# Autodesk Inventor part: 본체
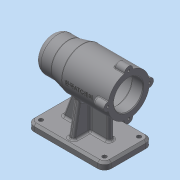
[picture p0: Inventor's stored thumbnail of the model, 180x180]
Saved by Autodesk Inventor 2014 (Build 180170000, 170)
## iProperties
Created: 2019-07
Part Number: 본체
Material: Generic
Document SubType Name: Modeling
Designer: mm
Density: 1 g/cm^3
Appearance: Default
Author: mm
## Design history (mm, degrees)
sketch "스케치1"
  geometry: L1 (-56, 35)-(56, 35); L2 (56, 35)-(56, -35); L3 (56, -35)-(-56, -35); L4 (-56, -35)-(-56, 35); L5 (-56, 35)-(56, -35); L6 (56, 35)-(-56, -35); 1 further point
  constraints: 12 end point, 2 midpoint, 2 parallel, 1 horizontal, 1 perpendicular
  dimensions: "d0" = 112 distance between parallel lines of L2 L4; "d1" = 70 distance between parallel lines of L3 L1
extrude "돌출1" new body sketch "스케치1" distance "d2" = 10; taper "d3" = 0 deg
sketch "스케치2"
  geometry: L1 (56, 80)-(-56, 80); L2 (56, 80)-(56, 105); L3 (56, 105)-(31, 105); L4 (31, 105)-(11, 110); L5 (11, 110)-(-56, 110); L6 (-56, 110)-(-56, 80); L7 (-56, 0)-(56, 0) reference; 1 further point
  constraints: 12 end point, 2 parallel, 2 perpendicular, 1 horizontal, 1 vertical alignment
  dimensions: "d4" = 50 diameter of L3 L1; "d5" = 60 diameter of L5 L1; "d6" = 25 distance from line of L3.end L2; "d7" = 45 distance from line of L4.end L2; "d8" = 80 distance from line of L7 L1.start; "d9" = 112 distance between parallel lines of L2 L6
revolve "회전1" sketch "스케치2" stored, may be unused: angle "d10" = 90 deg
sketch "스케치3"
  geometry: L1 (15.657, 80)-(-15.657, 80); L2 (15.657, 80)-(28, 10); L3 (-15.657, 80)-(-28, 10); L4 (28, 10)-(-28, 10); L5 (35, 0)-(-35, 0) reference; L6 (-35, 10)-(35, 10) reference; L7 (35, 0)-(35, 10) reference; 3 further points
  constraints: 8 end point, 2 midpoint, 1 collinear, 1 horizontal, 1 parallel, 1 vertical alignment
  dimensions: "d11" = 80 distance between parallel lines of L5 L1; "d12" = 100 deg angle of L2 L6; "d13" = 100 deg angle of L6 L3; "d14" = 7 distance from line of L2.end L7
extrude "돌출2" join sketch "스케치3" stored distance "d15" = 8; taper "d16" = 0 deg
sketch "스케치4"
  geometry: L1 (36, 10)-(10.522, 80); L2 (10.522, 80)-(-31, 80); L3 (-31, 80)-(-31, 10); L4 (36, 10)-(-31, 10); L5 (-56, 0)-(-56, 10) reference; L6 (56, 0)-(56, 10) reference; L7 (-56, 10)-(56, 10) reference; L8 (56, 0)-(-56, 0) reference; 1 further point
  constraints: 8 end point, 2 perpendicular, 1 collinear, 1 horizontal
  dimensions: "d17" = 25 distance from line of L3.end L5; "d18" = 20 distance from line of L1.start L6; "d19" = 110 deg angle of L1 L7; "d20" = 80 distance between parallel lines of L2 L8
extrude "돌출3" join sketch "스케치4" stored distance "d21" = 8; taper "d22" = 0 deg
sketch "스케치5"
  geometry: L1 (-56, 80)-(51, 80); L2 (51, 80)-(51, 90.5); L3 (51, 90.5)-(48, 90.5); L4 (48, 90.5)-(48, 96); L5 (48, 96)-(44, 96); L6 (44, 96)-(44, 97.5); L7 (44, 97.5)-(26, 97.5); L8 (26, 97.5)-(26, 101); L9 (26, 101)-(14, 101); L10 (14, 101)-(14, 104); L11 (14, 104)-(-40, 104); L12 (-40, 104)-(-40, 101); L13 (-40, 101)-(-56, 101); L14 (-56, 101)-(-56, 80); L15 (-56, 50)-(-56, 110) reference; L16 (56, 0)-(-56, 0) reference; 1 further point
  constraints: 28 end point, 10 parallel, 3 perpendicular, 1 collinear, 1 horizontal
  dimensions: "d23" = 48 diameter of L11 L1; "d24" = 42 diameter of L9 L1; "d25" = 42 diameter of L13 L1; "d26" = 35 diameter of L7 L1; "d27" = 32 diameter of L5 L1; "d28" = 21 diameter of L3 L1; "d29" = 3 distance between parallel lines of L4 L2; "d30" = 4 distance between parallel lines of L6 L4; "d31" = 18 distance between parallel lines of L8 L6; "d32" = 11.99959 distance between parallel lines of L10 L8; "d33" = 80 distance between parallel lines of L16 L1; "d34" = 16 distance between parallel lines of L12 L14; "d35" = 54 distance between parallel lines of L12 L10
revolve "회전2" sketch "스케치5" stored, may be unused: angle "d36" = 90 deg
sketch "스케치6"
  geometry: C1 r 21 at (0, 0) reference; C2 r 30 at (0, 0); C3 r 6 at (-30, 0); 2 further points
  constraints: 2 centre point, 2 horizontal alignment, 1 coincident, 1 other
  dimensions: "d37" = 60 diameter of C2; "d38" = 6 radius of C3
extrude "돌출4" join sketch "스케치6" distance "d39" = 16; taper "d40" = 0 deg
sketch "스케치7"
  geometry: A1 r 6 centre (0, 0) between (0.6, 5.97) and (0.6, -5.97) reference; 2 further points
  constraints: 1 coincident
hole "구멍1" sketch "스케치7" at (0, 0) diameter "d44" = 3.242; stored, may be unused: countersink angle "d48" = 90 deg, drill point angle "d50" = 118 deg; dims "d45" = 8, "d46" = 4, "d47" = 2, "d49" = 11
fillet "모깎기1" dims "d54" = 10
fillet "모깎기2" dims "d55" = 10
hole "구멍2" diameter "d58" = 6; stored, may be unused: countersink angle "d62" = 90 deg, drill point angle "d64" = 118 deg; dims "d56" = 10, "d57" = 10, "d59" = 8, "d60" = 4, "d61" = 2, "d63" = 11
chamfer "모따기1" distance "d71" = 1; stored, may be unused: second distance "d72" = 2, angle "d73" = 45 deg
fillet "모깎기3" dims "d74" = 3
fillet "모깎기4" dims "d75" = 3
fillet "모깎기5" dims "d76" = 1
fillet "모깎기6" dims "d77" = 3
fillet "모깎기7" dims "d78" = 3
fillet "모깎기8" dims "d79" = 3
chamfer "모따기2" distance "d80" = 3; stored, may be unused: second distance "d81" = 2, angle "d82" = 45 deg
fillet "모깎기9" dims "d83" = 0.3
fillet "모깎기10" dims "d84" = 3
node "작업 평면1"
sketch "스케치8"
  geometry: L1 (-11, 85)-(39, 85); L2 (39, 85)-(39, 75); L3 (39, 75)-(-11, 75); L4 (-11, 75)-(-11, 85); L5 (-11, 80)-(39, 80); L6 (14, 85)-(14, 75); L7 (46, 0)-(-46, 0) reference; L8 (56, 109.226)-(56, 86.771) reference; 1 further point
  constraints: 4 end point, 4 midpoint, 2 other
  dimensions: "d86" = 50 distance between parallel lines of L2 L4; "d87" = 10 distance between parallel lines of L3 L1; "d88" = 80 distance between parallel lines of L5 L7; "d89" = 42 distance between parallel lines of L6 L8
feature "엠보싱1" sketch "스케치8" dims "d0" = 112, "d1" = 70, "d11" = 80, "d12" = 100 deg, "d13" = 100 deg, "d14" = 7, "d90" = 0.5, "d91" = 0
node "솔리드1"
pattern_circular "원형 패턴1" dims angle "d42" = 360 deg
pattern_circular "원형 패턴2" dims angle "d52" = 360 deg
pattern_linear "직사각형 패턴1" dims "d67" = 92
other parameters: "d85" = -35
